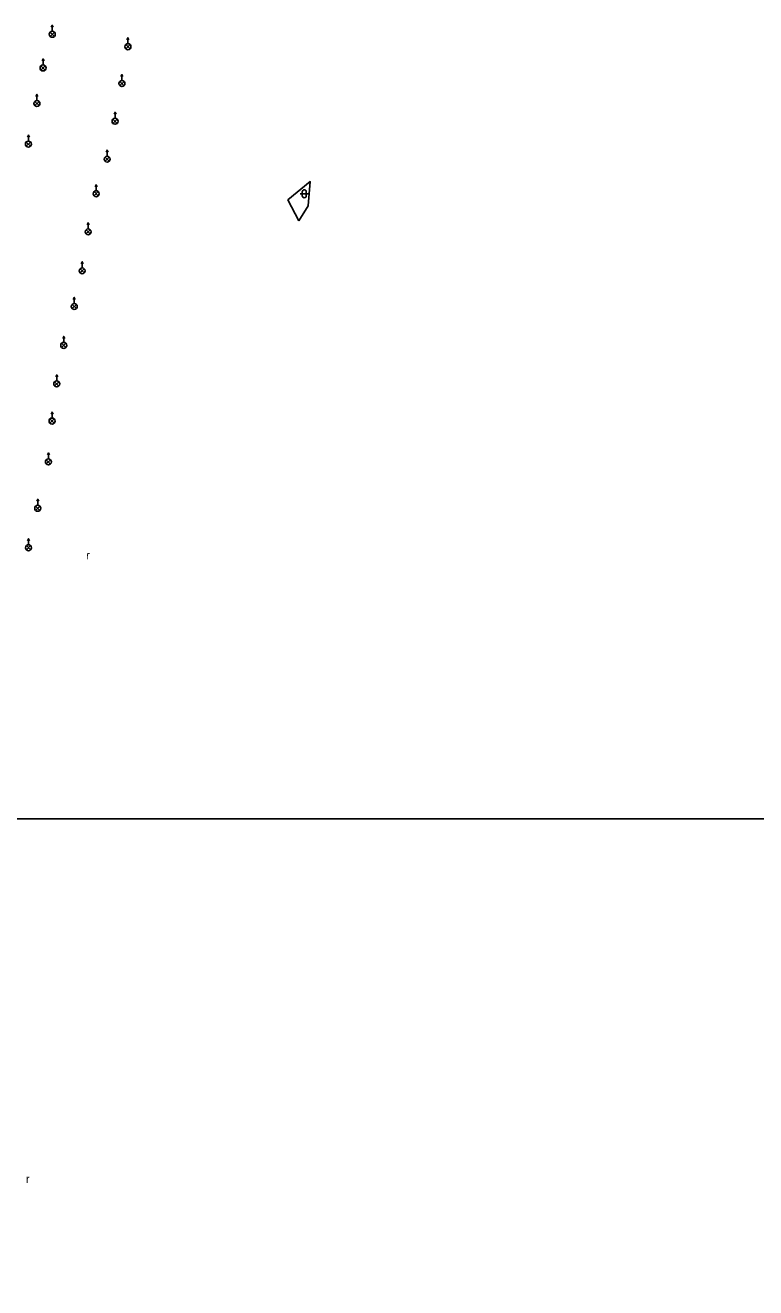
# Model space of a CAD drawing. Extents: x -582188 to -561562, y -1187250 to -1183500.
# Drawn here: x -578119.2 to -578027.9, y -1186808.6 to -1186650.8 of the extents above; entities that cross this region are included whole.
import ezdxf

# ---------------------------------------------------------------- set-up
doc = ezdxf.new("R2010")
doc.units = 0
for name, color, linetype in [('RÁMY_ML', 7, 'Continuous'), ('ZELEŇ', 7, 'Continuous'), ('ZN_BP', 7, 'Continuous'), ('ZN_KULTUR', 7, 'Continuous')]:
    doc.layers.add(name, color=color, linetype=linetype)

msp = doc.modelspace()

# ---------------------------------------------------------------- linework, layer by layer
at = {"layer": 'RÁMY_ML'}
msp.add_lwpolyline([(-578125, -1187000), (-577812.5, -1187000), (-577812.5, -1186750), (-578125, -1186750)], dxfattribs=at)
at = {"layer": 'ZELEŇ'}
msp.add_lwpolyline([(-578085.01, -1186675.28), (-578083.84, -1186673.41), (-578083.58, -1186670.38), (-578086.37, -1186672.67), (-578085.01, -1186675.28)], dxfattribs=at)
at = {"layer": 'ZN_BP'}
for p, q in [((-578115.83, -1186651.585), (-578115.83, -1186650.835)), ((-578116.095, -1186652.224), (-578115.566, -1186651.696)), ((-578115.566, -1186652.228), (-578116.095, -1186651.696)), ((-578106.37, -1186653.145), (-578106.37, -1186652.395)), ((-578106.635, -1186653.784), (-578106.106, -1186653.256)), ((-578106.106, -1186653.788), (-578106.635, -1186653.256)), ((-578116.99, -1186655.795), (-578116.99, -1186655.045)), ((-578117.255, -1186656.434), (-578116.726, -1186655.906)), ((-578116.726, -1186656.438), (-578117.255, -1186655.906)), ((-578107.12, -1186657.745), (-578107.12, -1186656.995)), ((-578107.385, -1186658.384), (-578106.856, -1186657.856)), ((-578106.856, -1186658.388), (-578107.385, -1186657.856)), ((-578118.015, -1186660.874), (-578117.486, -1186660.346)), ((-578117.486, -1186660.878), (-578118.015, -1186660.346)), ((-578117.75, -1186660.235), (-578117.75, -1186659.485)), ((-578107.98, -1186662.455), (-578107.98, -1186661.705)), ((-578108.245, -1186663.094), (-578107.716, -1186662.566)), ((-578107.716, -1186663.098), (-578108.245, -1186662.566)), ((-578118.82, -1186665.315), (-578118.82, -1186664.565)), ((-578119.085, -1186665.954), (-578118.556, -1186665.426)), ((-578118.556, -1186665.958), (-578119.085, -1186665.426)), ((-578108.97, -1186667.195), (-578108.97, -1186666.445)), ((-578109.235, -1186667.834), (-578108.706, -1186667.306)), ((-578108.706, -1186667.838), (-578109.235, -1186667.306)), ((-578110.35, -1186671.515), (-578110.35, -1186670.765)), ((-578110.615, -1186672.154), (-578110.086, -1186671.626)), ((-578110.086, -1186672.158), (-578110.615, -1186671.626)), ((-578111.35, -1186676.275), (-578111.35, -1186675.525)), ((-578111.615, -1186676.914), (-578111.086, -1186676.386)), ((-578111.086, -1186676.918), (-578111.615, -1186676.386)), ((-578112.09, -1186681.145), (-578112.09, -1186680.395)), ((-578112.355, -1186681.784), (-578111.826, -1186681.256)), ((-578111.826, -1186681.788), (-578112.355, -1186681.256)), ((-578113.345, -1186686.244), (-578112.816, -1186685.716)), ((-578112.816, -1186686.248), (-578113.345, -1186685.716)), ((-578113.08, -1186685.605), (-578113.08, -1186684.855)), ((-578114.4, -1186690.465), (-578114.4, -1186689.715)), ((-578114.665, -1186691.104), (-578114.136, -1186690.576)), ((-578114.136, -1186691.108), (-578114.665, -1186690.576)), ((-578115.27, -1186695.275), (-578115.27, -1186694.525)), ((-578115.535, -1186695.914), (-578115.006, -1186695.386)), ((-578115.006, -1186695.918), (-578115.535, -1186695.386)), ((-578115.86, -1186699.925), (-578115.86, -1186699.175)), ((-578116.125, -1186700.564), (-578115.596, -1186700.036)), ((-578115.596, -1186700.568), (-578116.125, -1186700.036)), ((-578116.32, -1186705.025), (-578116.32, -1186704.275)), ((-578116.585, -1186705.664), (-578116.056, -1186705.136)), ((-578116.056, -1186705.668), (-578116.585, -1186705.136)), ((-578117.915, -1186711.464), (-578117.386, -1186710.936)), ((-578117.386, -1186711.468), (-578117.915, -1186710.936)), ((-578117.65, -1186710.825), (-578117.65, -1186710.075)), ((-578118.8, -1186715.755), (-578118.8, -1186715.005)), ((-578119.065, -1186716.394), (-578118.536, -1186715.866)), ((-578118.536, -1186716.398), (-578119.065, -1186715.866))]:
    msp.add_line(p, q, dxfattribs=at)
for points in [[(-578115.955, -1186651.085), (-578115.83, -1186650.835), (-578115.705, -1186651.085)], [(-578106.495, -1186652.645), (-578106.37, -1186652.395), (-578106.245, -1186652.645)], [(-578117.115, -1186655.295), (-578116.99, -1186655.045), (-578116.865, -1186655.295)], [(-578107.245, -1186657.245), (-578107.12, -1186656.995), (-578106.995, -1186657.245)], [(-578117.875, -1186659.735), (-578117.75, -1186659.485), (-578117.625, -1186659.735)], [(-578108.105, -1186661.955), (-578107.98, -1186661.705), (-578107.855, -1186661.955)], [(-578118.945, -1186664.815), (-578118.82, -1186664.565), (-578118.695, -1186664.815)], [(-578109.095, -1186666.695), (-578108.97, -1186666.445), (-578108.845, -1186666.695)], [(-578110.475, -1186671.015), (-578110.35, -1186670.765), (-578110.225, -1186671.015)], [(-578111.475, -1186675.775), (-578111.35, -1186675.525), (-578111.225, -1186675.775)], [(-578112.215, -1186680.645), (-578112.09, -1186680.395), (-578111.965, -1186680.645)], [(-578113.205, -1186685.105), (-578113.08, -1186684.855), (-578112.955, -1186685.105)], [(-578114.525, -1186689.965), (-578114.4, -1186689.715), (-578114.275, -1186689.965)], [(-578115.395, -1186694.775), (-578115.27, -1186694.525), (-578115.145, -1186694.775)], [(-578115.985, -1186699.425), (-578115.86, -1186699.175), (-578115.735, -1186699.425)], [(-578116.445, -1186704.525), (-578116.32, -1186704.275), (-578116.195, -1186704.525)], [(-578117.775, -1186710.325), (-578117.65, -1186710.075), (-578117.525, -1186710.325)], [(-578118.925, -1186715.255), (-578118.8, -1186715.005), (-578118.675, -1186715.255)]]:
    msp.add_lwpolyline(points, dxfattribs=at)
for centre in [(-578115.83, -1186651.96), (-578106.37, -1186653.52), (-578116.99, -1186656.17), (-578107.12, -1186658.12), (-578117.75, -1186660.61), (-578107.98, -1186662.83), (-578118.82, -1186665.69), (-578108.97, -1186667.57), (-578110.35, -1186671.89), (-578111.35, -1186676.65), (-578112.09, -1186681.52), (-578113.08, -1186685.98), (-578114.4, -1186690.84), (-578115.27, -1186695.65), (-578115.86, -1186700.3), (-578116.32, -1186705.4), (-578117.65, -1186711.2), (-578118.8, -1186716.13)]:
    msp.add_circle(centre, 0.375, dxfattribs=at)
at = {"layer": 'ZN_KULTUR'}
for p, q in [((-578084.83, -1186671.9), (-578083.83, -1186671.9)), ((-578084.58, -1186672.15), (-578084.58, -1186671.65)), ((-578084.08, -1186672.15), (-578084.08, -1186671.65))]:
    msp.add_line(p, q, dxfattribs=at)
for centre, start, end in [((-578084.33, -1186671.65), 0, 179.99999), ((-578084.33, -1186672.15), 179.99999, 359.99999)]:
    msp.add_arc(centre, 0.25, start, end, dxfattribs=at)

# ---------------------------------------------------------------- texts
for p in [(-578111.598, -1186717.562), (-578119.108, -1186795.502)]:
    msp.add_text('r', height=1, dxfattribs=at).set_placement(p)

doc.saveas('drawing.dxf')
